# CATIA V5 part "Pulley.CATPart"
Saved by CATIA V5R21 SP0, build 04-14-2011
Part number: Pulley
Bounding box of the stored display mesh (mm): x -40.838 to 40.838, y -33 to 33, z -40.838 to 40.838
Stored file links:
  D:\CATIA V5R21 E-RESOURCES\CATIA-V5R21\catia-v5r21-Prts\c12_catia_v5r21_prt\c12_catia_v5r21figr_12-49\Pulley.CATPart
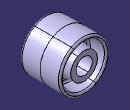
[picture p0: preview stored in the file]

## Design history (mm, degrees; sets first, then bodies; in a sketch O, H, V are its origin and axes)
Body1 (main body)
  Sketch1 on yz-plane, origin (0, 0, 0), H (0, 1, 0), V (0, 0, 1)
    line L1 (0, 13.45) -> (31.5, 13.45)
    point P1 (0, 13.45)
    point P2 (31.5, 13.45)
    line L2 (31.5, 13.45) -> (31.5, 22)
    point P3 (31.5, 22)
    line L3 (31.5, 22) -> (6, 24)
    point P4 (6, 24)
    line L4 (6, 24) -> (6, 33)
    point P5 (6, 33)
    line L5 (6, 33) -> (33, 35)
    point P6 (33, 35)
    line L6 (33, 35) -> (33, 41)
    point P7 (33, 41)
    line L7 (33, 41) -> (0, 41)
    point P8 (0, 41)
    point P9 (0, 41)
    point P10 (-33, 41)
    line L8 (-33, 41) -> (0, 41)
    point P11 (-33, 35)
    line L9 (-33, 35) -> (-33, 41)
    point P12 (-6, 33)
    line L10 (-6, 33) -> (-33, 35)
    point P13 (-6, 24)
    line L11 (-6, 24) -> (-6, 33)
    point P14 (-31.5, 22)
    line L12 (-31.5, 22) -> (-6, 24)
    point P15 (-31.5, 13.45)
    line L13 (-31.5, 13.45) -> (-31.5, 22)
    point P16 (0, 13.45)
    line L14 (0, 13.45) -> (-31.5, 13.45)
    length L1 = 31.5
    distance L1 H = 13.45
    distance P4 H = 24
    distance P3 H = 22
    distance L4 V = 6
    distance P5 H = 33
    distance P6 H = 35
    distance V L6 = 33
    distance L7 H = 41
    coincidence: P1 V, P8 V, P1 P16, P8 P9
    horizontal: L1 H, L7 H
    vertical: L2 V, L4 V, L6 V
    symmetry: P8 P9 V, P7 P10 V, L7 L8 V, P6 P11 V, L6 L9 V, P5 P12 V, L5 L10 V, P4 P13 V, L4 L11 V, P3 P14 V, L3 L12 V, P2 P15 V, L2 L13 V, P1 P16 V, L1 L14 V
  Shaft1: profile Sketch1, axis Sketch1.H, angle 360
  Fillet1: radius 3, on 4 faces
